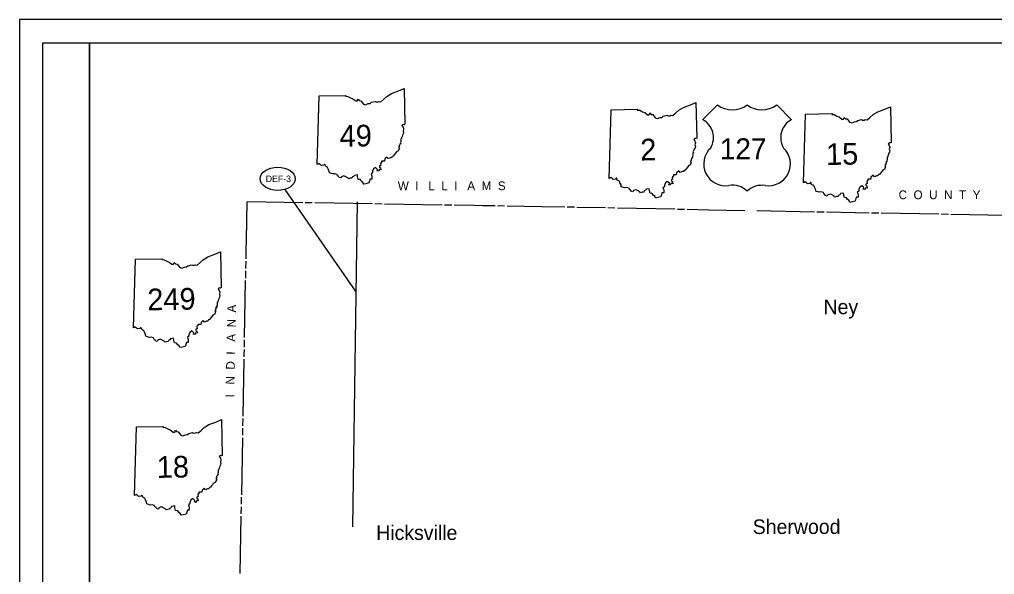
# Model space of a CAD drawing. Extents: x 0 to 419, y 0 to 220.
# Drawn here: x 0 to 208.9, y 101 to 220 of the extents above; entities that cross this region are included whole.
import ezdxf

# ---------------------------------------------------------------- set-up
doc = ezdxf.new("R2010")
doc.units = 0
for name, color, linetype in [('GM_X_County', 7, 'Continuous'), ('Level 12', 7, 'Continuous'), ('Level 13', 7, 'Continuous'), ('PV_P_Text', 7, 'Continuous'), ('SH_Border', 7, 'Continuous'), ('SH_Cut_Line', 7, 'Continuous'), ('SH_Text', 7, 'Continuous')]:
    doc.layers.add(name, color=color, linetype=linetype)

msp = doc.modelspace()

# ---------------------------------------------------------------- linework, layer by layer
at = {"layer": 'GM_X_County'}
for points in [[(48.62, 172.78), (48.77, 180.9)], [(60.67, 180.72), (48.77, 180.91)], [(62.74, 180.68), (61.19, 180.71)], [(75.61, 180.47), (63.25, 180.67)], [(77.67, 180.43), (76.12, 180.46)], [(90.54, 180.22), (78.19, 180.42)], [(92.61, 180.18), (91.06, 180.21)], [(99.3, 180.07), (97.38, 180.1), (93.12, 180.17)], [(101.88, 180.02), (99.3, 180.07)], [(103.94, 179.99), (102.4, 180.01)], [(111.91, 179.85), (104.46, 179.98)], [(116.81, 179.76), (111.91, 179.85)], [(118.88, 179.73), (117.33, 179.76)], [(125.57, 179.61), (119.4, 179.72)], [(127.57, 179.57), (126.03, 179.6)], [(140.44, 179.3), (128.09, 179.56)], [(142.51, 179.25), (140.96, 179.29)], [(155.38, 179), (147.59, 179.15), (143.02, 179.24)], [(170.31, 178.71), (157.96, 178.95)], [(172.38, 178.67), (170.83, 178.7)], [(179.07, 178.54), (172.89, 178.66)], [(182.03, 178.49), (179.1, 178.54)], [(184.1, 178.46), (182.55, 178.48)], [(196.97, 178.24), (184.61, 178.45)], [(199.03, 178.21), (197.48, 178.23)], [(211.47, 178), (199.55, 178.2)], [(48.58, 170.62), (48.62, 172.78)], [(48.54, 168.68), (48.58, 170.62)], [(48.5, 166.62), (48.53, 168.16)], [(48.46, 164.56), (48.49, 166.1)], [(48.23, 151.82), (48.45, 164.04)], [(48.19, 149.76), (48.22, 151.3)], [(48.16, 148.14), (48.18, 149.25)], [(47.91, 134.96), (48.14, 147.19)], [(48.15, 147.7), (48.16, 148.14)], [(47.87, 132.91), (47.9, 134.44)], [(47.83, 130.84), (47.86, 132.39)], [(47.6, 118.11), (47.83, 130.33)], [(47.56, 116.05), (47.59, 117.59)], [(47.52, 113.99), (47.55, 115.54)], [(47.28, 101.25), (47.51, 113.48)]]:
    msp.add_lwpolyline(points, dxfattribs=at)
at = {"layer": 'Level 12'}
msp.add_line((71.44, 111.2), (72.44, 180.93), dxfattribs=at)
at = {"layer": 'Level 13'}
msp.add_line((72.16, 161.64), (56.92, 183.57), dxfattribs=at)
msp.add_ellipse((55.34, 185.84), major_axis=(3.75, 0), ratio=0.666667, dxfattribs=at)
at = {"layer": 'PV_P_Text'}
for p, q in [((149.55, 201.71), (146.36, 198.52)), ((165.42, 198.52), (162.23, 201.71))]:
    msp.add_line(p, q, dxfattribs=at)
for centre, radius, start, end in [((152.72, 205.74), 5.13, 231.813, 308.187), ((159.06, 205.74), 5.13, 231.813, 308.187), ((144.36, 194.67), 4.34, 329.1175, 62.6108), ((167.42, 194.67), 4.34, 117.3892, 210.8825), ((151.28, 189.02), 4.68, 133.0046, 278.7282), ((160.5, 189.02), 4.68, 261.2718, 46.9954), ((160.5, 189.02), 4.68, 261.2718, 46.9954), ((152.85, 180.29), 4.19, 43.4177, 101.8742), ((159.02, 180.01), 4.44, 79.9613, 134.7468)]:
    msp.add_arc(centre, radius, start, end, dxfattribs=at)
at = {"layer": 'SH_Border'}
for points in [[(5, 215), (15, 215), (15, 5), (5, 5)], [(15, 215), (335, 215), (335, 5), (15, 5)]]:
    msp.add_lwpolyline(points, close=True, dxfattribs=at)
at = {"layer": 'SH_Cut_Line'}
msp.add_lwpolyline([(0, 0), (340, 0), (340, 220), (0, 220)], close=True, dxfattribs=at)
at = {"layer": 'SH_Text'}
for p, q in [((63.8, 188.9), (64.21, 203.64)), ((126.33, 185.93), (126.74, 200.66)), ((167.98, 185), (168.39, 199.73)), ((24.44, 153.87), (24.85, 168.61)), ((24.66, 117.91), (25.07, 132.65))]:
    msp.add_line(p, q, dxfattribs=at)
for points in [[(64.21, 203.64), (69.93, 203.73), (69.84, 203.55), (70.38, 203.52), (70.95, 203.2), (71.43, 203), (72.03, 202.53), (72.38, 202.54), (72.53, 202.92), (72.8, 202.63), (73.13, 202.57), (73.68, 201.87), (74.14, 201.72), (74.7, 201.96), (75.11, 202), (75.41, 202.24), (76.19, 202.44), (76.41, 202.32), (76.83, 202.34), (77.04, 202.43), (77.4, 202.35), (78.04, 202.89), (78.69, 203.52), (79.7, 204.12), (81.21, 204.68), (82.4, 205.19), (82.58, 197.54)], [(126.74, 200.66), (132.46, 200.76), (132.37, 200.58), (132.91, 200.54), (133.48, 200.23), (133.97, 200.03), (134.56, 199.56), (134.92, 199.57), (135.07, 199.95), (135.34, 199.65), (135.66, 199.6), (136.22, 198.9), (136.68, 198.74), (137.23, 198.98), (137.64, 199.02), (137.94, 199.26), (138.73, 199.47), (138.94, 199.35), (139.36, 199.37), (139.57, 199.46), (139.93, 199.38), (140.57, 199.92), (141.23, 200.55), (142.23, 201.14), (143.74, 201.71), (144.94, 202.21), (145.11, 194.57)], [(168.39, 199.73), (174.11, 199.83), (174.02, 199.65), (174.56, 199.61), (175.13, 199.3), (175.61, 199.1), (176.21, 198.63), (176.56, 198.64), (176.71, 199.02), (176.98, 198.73), (177.31, 198.67), (177.86, 197.97), (178.32, 197.81), (178.87, 198.06), (179.29, 198.1), (179.59, 198.33), (180.37, 198.54), (180.59, 198.42), (181.01, 198.44), (181.22, 198.53), (181.58, 198.45), (182.22, 198.99), (182.87, 199.62), (183.88, 200.21), (185.39, 200.78), (186.58, 201.28), (186.75, 193.64)], [(82.58, 197.54), (82.4, 197.43), (82.13, 197.48), (81.94, 197.27), (82.17, 196.91), (82.28, 196.53), (82.18, 196.12), (82.28, 195.77), (82.21, 195.48), (82.04, 195.2), (81.98, 194.92), (81.83, 194.64), (81.85, 194.48), (81.71, 194.35), (81.73, 193.87), (81.66, 193.61), (81.69, 193.38), (81.46, 193.32), (81.51, 193.13), (81.37, 192.98), (81.4, 192.73), (81.23, 192.57), (81.39, 192.25), (81.27, 192.15), (81.16, 191.76), (80.87, 191.68), (80.29, 190.97), (80.08, 190.7), (79.85, 190.63), (79.73, 190.35), (79.44, 190.35), (79.01, 190.16), (78.73, 190.49), (78.25, 190.09), (78.19, 189.63), (77.58, 189.65), (77.6, 189.41), (77.46, 189.35), (77.34, 189.11), (77.41, 188.7), (77.12, 188.59), (77.16, 188.35), (77.34, 188.21), (77.42, 187.75), (77.12, 187.84), (76.87, 187.45), (76.61, 187.55), (76.69, 187.87), (76.26, 188.27), (75.85, 187.95), (75.63, 187.45), (75.63, 187.11), (75.32, 186.9), (75.52, 186.42), (75.48, 186.09), (75.49, 185.78), (75.11, 185.79), (74.87, 184.95)], [(145.11, 194.57), (144.93, 194.46), (144.66, 194.51), (144.47, 194.29), (144.7, 193.94), (144.81, 193.56), (144.71, 193.14), (144.81, 192.8), (144.74, 192.51), (144.57, 192.22), (144.51, 191.95), (144.37, 191.66), (144.38, 191.5), (144.24, 191.38), (144.26, 190.9), (144.19, 190.63), (144.22, 190.4), (143.99, 190.34), (144.04, 190.15), (143.9, 190.01), (143.93, 189.76), (143.77, 189.6), (143.93, 189.28), (143.8, 189.17), (143.69, 188.78), (143.4, 188.71), (142.82, 187.99), (142.62, 187.72), (142.38, 187.65), (142.26, 187.38), (141.97, 187.38), (141.54, 187.18), (141.27, 187.52), (140.78, 187.12), (140.72, 186.66), (140.11, 186.67), (140.13, 186.44), (140, 186.37), (139.87, 186.14), (139.94, 185.73), (139.66, 185.62), (139.69, 185.38), (139.88, 185.23), (139.96, 184.77), (139.65, 184.87), (139.4, 184.48), (139.14, 184.57), (139.23, 184.9), (138.79, 185.29), (138.38, 184.98), (138.16, 184.47), (138.16, 184.13), (137.85, 183.93), (138.05, 183.45), (138.02, 183.12), (138.02, 182.81), (137.64, 182.82), (137.41, 181.97)], [(186.75, 193.64), (186.58, 193.53), (186.3, 193.58), (186.12, 193.37), (186.35, 193.01), (186.46, 192.63), (186.36, 192.21), (186.45, 191.87), (186.39, 191.58), (186.22, 191.3), (186.16, 191.02), (186.01, 190.73), (186.03, 190.57), (185.89, 190.45), (185.91, 189.97), (185.84, 189.7), (185.86, 189.47), (185.64, 189.41), (185.69, 189.23), (185.55, 189.08), (185.58, 188.83), (185.41, 188.67), (185.57, 188.35), (185.44, 188.25), (185.34, 187.86), (185.05, 187.78), (184.47, 187.06), (184.26, 186.79), (184.03, 186.73), (183.9, 186.45), (183.62, 186.45), (183.19, 186.26), (182.91, 186.59), (182.43, 186.19), (182.37, 185.73), (181.76, 185.74), (181.78, 185.51), (181.64, 185.44), (181.52, 185.21), (181.59, 184.8), (181.3, 184.69), (181.34, 184.45), (181.52, 184.3), (181.6, 183.85), (181.3, 183.94), (181.05, 183.55), (180.79, 183.64), (180.87, 183.97), (180.44, 184.36), (180.03, 184.05), (179.81, 183.55), (179.81, 183.21), (179.5, 183), (179.7, 182.52), (179.66, 182.19), (179.67, 181.88), (179.28, 181.89), (179.05, 181.04)], [(74.87, 184.95), (74.21, 184.78), (73.74, 184.69), (73.58, 185.07), (73.25, 185.27), (73.03, 185.66), (72.56, 185.71), (72.44, 186.24), (72.39, 186.68), (71.74, 186.57), (71.56, 186.31), (71.33, 186.23), (71.2, 185.97), (70.88, 185.95), (70.55, 185.82), (70.32, 186.08), (69.77, 186.34), (69.52, 186.48), (69, 186.27), (68.89, 186.02), (68.48, 186.13), (68.38, 186.41), (68.13, 186.49), (68.08, 186.78), (67.54, 186.94), (67.13, 186.88), (66.41, 187.11), (66.37, 187.5), (66.12, 187.97), (65.99, 188.3), (65.54, 188.55), (65.44, 188.94), (65.3, 188.92), (65.17, 188.77), (64.66, 188.69), (64.46, 188.85), (64.17, 189.12), (63.8, 188.9)], [(137.41, 181.97), (136.74, 181.81), (136.28, 181.71), (136.11, 182.1), (135.78, 182.3), (135.56, 182.69), (135.09, 182.74), (134.98, 183.27), (134.92, 183.7), (134.27, 183.6), (134.09, 183.33), (133.86, 183.26), (133.73, 183), (133.42, 182.97), (133.08, 182.85), (132.86, 183.11), (132.3, 183.37), (132.06, 183.51), (131.54, 183.3), (131.43, 183.05), (131.01, 183.16), (130.92, 183.43), (130.67, 183.52), (130.61, 183.81), (130.08, 183.97), (129.67, 183.9), (128.94, 184.14), (128.9, 184.53), (128.65, 185), (128.53, 185.32), (128.07, 185.57), (127.98, 185.96), (127.83, 185.95), (127.7, 185.79), (127.19, 185.72), (126.99, 185.88), (126.7, 186.15), (126.33, 185.93)], [(179.05, 181.04), (178.38, 180.88), (177.92, 180.78), (177.76, 181.17), (177.43, 181.37), (177.21, 181.76), (176.74, 181.81), (176.62, 182.34), (176.57, 182.77), (175.92, 182.67), (175.74, 182.4), (175.51, 182.33), (175.38, 182.07), (175.06, 182.04), (174.72, 181.92), (174.5, 182.18), (173.95, 182.44), (173.7, 182.58), (173.18, 182.37), (173.07, 182.12), (172.66, 182.23), (172.56, 182.51), (172.31, 182.59), (172.26, 182.88), (171.72, 183.04), (171.31, 182.98), (170.59, 183.21), (170.55, 183.6), (170.3, 184.07), (170.17, 184.4), (169.72, 184.65), (169.62, 185.03), (169.48, 185.02), (169.34, 184.86), (168.84, 184.79), (168.63, 184.95), (168.35, 185.22), (167.98, 185)], [(24.85, 168.61), (30.57, 168.71), (30.48, 168.53), (31.02, 168.49), (31.59, 168.18), (32.08, 167.98), (32.67, 167.51), (33.02, 167.51), (33.17, 167.9), (33.44, 167.6), (33.77, 167.55), (34.32, 166.84), (34.78, 166.69), (35.34, 166.93), (35.75, 166.97), (36.05, 167.21), (36.83, 167.41), (37.05, 167.29), (37.47, 167.32), (37.68, 167.41), (38.04, 167.33), (38.68, 167.86), (39.33, 168.49), (40.34, 169.09), (41.85, 169.65), (43.04, 170.16), (43.22, 162.51)], [(43.22, 162.51), (43.04, 162.41), (42.77, 162.46), (42.58, 162.24), (42.81, 161.88), (42.92, 161.51), (42.82, 161.09), (42.92, 160.74), (42.85, 160.46), (42.68, 160.17), (42.62, 159.9), (42.47, 159.61), (42.49, 159.45), (42.35, 159.32), (42.37, 158.84), (42.3, 158.58), (42.33, 158.35), (42.1, 158.29), (42.15, 158.1), (42.01, 157.96), (42.04, 157.7), (41.87, 157.54), (42.03, 157.22), (41.91, 157.12), (41.8, 156.73), (41.51, 156.65), (40.93, 155.94), (40.72, 155.67), (40.49, 155.6), (40.37, 155.32), (40.08, 155.32), (39.65, 155.13), (39.37, 155.46), (38.89, 155.06), (38.83, 154.6), (38.22, 154.62), (38.24, 154.39), (38.1, 154.32), (37.98, 154.09), (38.05, 153.67), (37.76, 153.57), (37.8, 153.33), (37.98, 153.18), (38.06, 152.72), (37.76, 152.81), (37.51, 152.43), (37.25, 152.52), (37.33, 152.85), (36.9, 153.24), (36.49, 152.92), (36.27, 152.42), (36.27, 152.08), (35.96, 151.88), (36.16, 151.4), (36.12, 151.07), (36.13, 150.75), (35.75, 150.76), (35.51, 149.92)], [(35.51, 149.92), (34.85, 149.76), (34.38, 149.66), (34.22, 150.04), (33.89, 150.25), (33.67, 150.63), (33.2, 150.69), (33.08, 151.22), (33.03, 151.65), (32.38, 151.54), (32.2, 151.28), (31.97, 151.21), (31.84, 150.94), (31.52, 150.92), (31.19, 150.8), (30.97, 151.06), (30.41, 151.32), (30.16, 151.45), (29.64, 151.24), (29.53, 150.99), (29.12, 151.1), (29.02, 151.38), (28.77, 151.46), (28.72, 151.76), (28.18, 151.91), (27.77, 151.85), (27.05, 152.09), (27.01, 152.47), (26.76, 152.94), (26.63, 153.27), (26.18, 153.52), (26.08, 153.91), (25.94, 153.9), (25.81, 153.74), (25.3, 153.67), (25.1, 153.83), (24.81, 154.1), (24.44, 153.87)], [(25.07, 132.65), (30.79, 132.74), (30.7, 132.56), (31.24, 132.53), (31.81, 132.21), (32.3, 132.01), (32.89, 131.55), (33.25, 131.55), (33.4, 131.93), (33.67, 131.64), (33.99, 131.59), (34.55, 130.88), (35.01, 130.73), (35.56, 130.97), (35.97, 131.01), (36.27, 131.25), (37.06, 131.45), (37.28, 131.33), (37.69, 131.35), (37.9, 131.44), (38.26, 131.36), (38.9, 131.9), (39.56, 132.53), (40.57, 133.13), (42.07, 133.69), (43.27, 134.2), (43.44, 126.55)], [(43.44, 126.55), (43.26, 126.44), (42.99, 126.49), (42.81, 126.28), (43.03, 125.92), (43.14, 125.54), (43.05, 125.13), (43.14, 124.78), (43.08, 124.5), (42.9, 124.21), (42.84, 123.94), (42.7, 123.65), (42.71, 123.49), (42.57, 123.36), (42.6, 122.88), (42.52, 122.62), (42.55, 122.39), (42.32, 122.33), (42.37, 122.14), (42.23, 121.99), (42.26, 121.74), (42.1, 121.58), (42.26, 121.26), (42.13, 121.16), (42.02, 120.77), (41.73, 120.69), (41.15, 119.98), (40.95, 119.71), (40.72, 119.64), (40.59, 119.36), (40.31, 119.36), (39.88, 119.17), (39.6, 119.5), (39.11, 119.1), (39.06, 118.64), (38.44, 118.66), (38.46, 118.42), (38.33, 118.36), (38.2, 118.12), (38.27, 117.71), (37.99, 117.61), (38.02, 117.37), (38.21, 117.22), (38.29, 116.76), (37.98, 116.85), (37.73, 116.47), (37.47, 116.56), (37.56, 116.88), (37.12, 117.28), (36.71, 116.96), (36.5, 116.46), (36.49, 116.12), (36.19, 115.91), (36.38, 115.43), (36.35, 115.1), (36.35, 114.79), (35.97, 114.8), (35.74, 113.96)], [(35.74, 113.96), (35.07, 113.79), (34.61, 113.7), (34.44, 114.08), (34.11, 114.28), (33.9, 114.67), (33.42, 114.72), (33.31, 115.26), (33.25, 115.69), (32.6, 115.58), (32.43, 115.32), (32.2, 115.25), (32.06, 114.98), (31.75, 114.96), (31.41, 114.83), (31.19, 115.09), (30.64, 115.36), (30.39, 115.49), (29.87, 115.28), (29.76, 115.03), (29.34, 115.14), (29.25, 115.42), (29, 115.5), (28.94, 115.8), (28.41, 115.95), (28, 115.89), (27.28, 116.13), (27.23, 116.51), (26.99, 116.98), (26.86, 117.31), (26.4, 117.56), (26.31, 117.95), (26.16, 117.94), (26.03, 117.78), (25.52, 117.71), (25.32, 117.86), (25.04, 118.14), (24.66, 117.91)]]:
    msp.add_lwpolyline(points, dxfattribs=at)

# ---------------------------------------------------------------- texts
at = {"layer": 'Level 13'}
msp.add_text('DEF-3', height=1.4, dxfattribs=at).set_placement((52.76, 185.14))
at = {"layer": 'PV_P_Text'}
msp.add_text('127', height=4.489, dxfattribs=at).set_placement((150.04, 190.04))
at = {"layer": 'SH_Text'}
for s, height, rotation, p in [('49', 4.646, 1.0142, (68.62, 192.69)), ('2', 4.65, 1.0142, (133.03, 189.75)), ('15', 4.646, 1.0142, (172.83, 188.79)), ('W  I   L  L  I   A  M  S', 1.8731, 0.047, (81.05, 183.39)), ('C  O  U  N  T  Y', 1.8731, 0.0403, (188.35, 181.47)), ('249', 4.646, 1.0142, (27.41, 157.63)), ('I   N  D  I   A  N  A', 1.8726, 88.8743, (46, 138.94)), ('Ney', 3.122, 0.0399, (172.26, 156.81)), ('18', 4.646, 1.0142, (29.45, 121.7)), ('Sherwood', 3.122, 0.0399, (157.1, 109.68)), ('Hicksville', 3.122, 0.052, (76.42, 108.39))]:
    msp.add_text(s, height=height, rotation=rotation, dxfattribs=at).set_placement(p)

doc.saveas('drawing.dxf')
